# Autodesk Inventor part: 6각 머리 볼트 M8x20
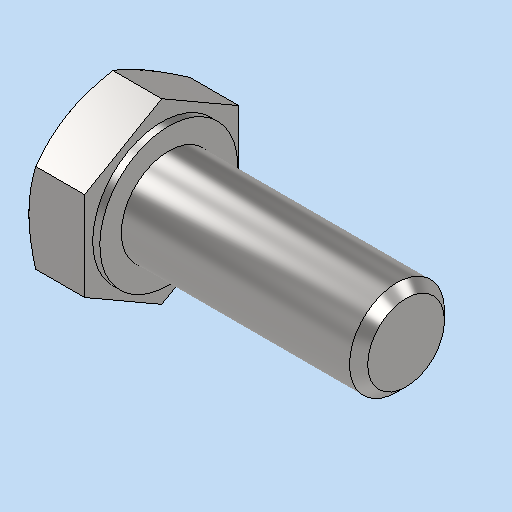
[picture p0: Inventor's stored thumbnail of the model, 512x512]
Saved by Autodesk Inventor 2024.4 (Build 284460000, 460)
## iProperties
Created: 2025-11
Part Number: 6각 머리 볼트 M8x20
Material: 강철, 연강
Description: 6각 머리 볼트 및 6각 머리 나사
Document SubType Name: Modeling
Designer: home
Density: 7.85 g/cm^3
Appearance: 기본값
Author: jhkim
Sending System: Autodesk Inventor 2026
Preprocessor: ST-DEVELOPER v20.1
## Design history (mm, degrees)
feature "Solid1"
node "솔리드1"
